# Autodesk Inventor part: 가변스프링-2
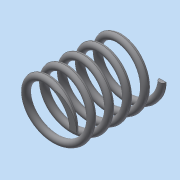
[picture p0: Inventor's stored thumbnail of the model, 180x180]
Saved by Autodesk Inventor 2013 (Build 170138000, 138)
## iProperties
Created: 2018-10
Part Number: 가변스프링-2
Material: 일반
Document SubType Name: Modeling
Designer: Administrator
Density: 1 g/cm^3
Mass: 0.776002 g
Surface Area: 15.7676 cm^2
Volume: 0.776002 cm^3
Author: Administrator
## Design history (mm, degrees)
sketch "스케치1"
  geometry: L1 (0, 0)-(0, 25.572); L2 (0, 0)-(8, 0); L3 (0, 25.572)-(8, 25.572); C1 r 1 at (8, 0)
  constraints: 6 end point, 1 centre point, 1 coincident, 1 parallel, 1 perpendicular, 1 vertical
  dimensions: "d0" = 25.57164 distance of L1.start L1.end (derived); "d1" = 8 distance of L1.start L2.end; "d2" = 8 distance of L1.end L3.end; "d3" = 2 diameter of C1
feature "코일1" sketch "스케치1" pitch "d4" = 10; turns "d6" = 5; dims "d5" = 25.57164 (= d0), "d7" = 0, angle "d8" = 90 deg, angle "d9" = 90 deg, "d10" = 0, "d11" = 0
sketch "스케치2"
  geometry: L1 (25.572, 11.5)-(0, 11.5); L2 (0, 11.5)-(0, -11.5); L3 (0, -11.5)-(25.572, -11.5); L4 (25.572, -11.5)-(25.572, 11.5); 2 further points
  constraints: 8 end point, 2 parallel, 1 coincident, 1 horizontal, 1 midpoint, 1 perpendicular
  dimensions: "d12" = 25.57164 distance between parallel lines of L2 L4 (derived); "d14" = 23 distance between parallel lines of L1 L3
extrude "돌출1" sketch "스케치2" stored distance "d15" = 0; taper "d16" = 0 deg
node "솔리드1"
